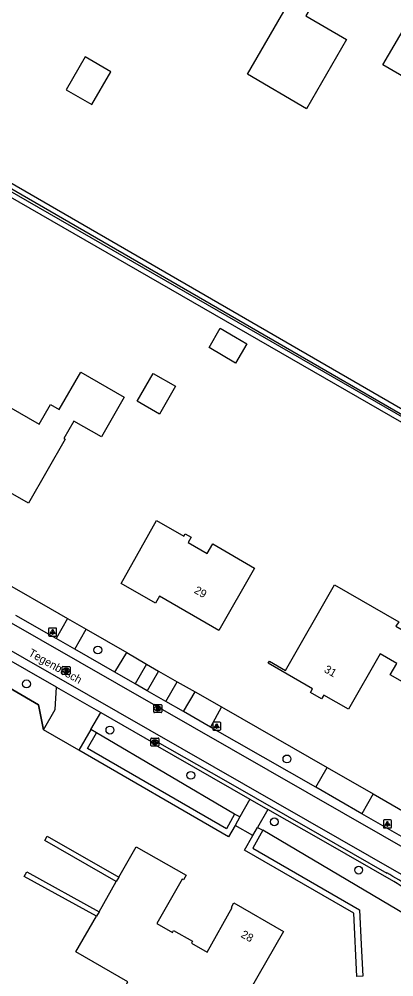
# Model space of a CAD drawing. Extents: x 156502 to 159074, y 384229 to 386094.
# Drawn here: x 157105.6 to 157152.4, y 385707.8 to 385827.5 of the extents above; entities that cross this region are included whole.
import ezdxf

# ---------------------------------------------------------------- set-up
doc = ezdxf.new("R2010")
doc.units = 0
for name, color, linetype in [('IMGEO_Berm_groen', 7, 'Continuous'), ('IMGEO_Berm_open', 7, 'Continuous'), ('IMGEO_Boom', 7, 'Continuous'), ('IMGEO_Brandkraan', 7, 'Continuous'), ('IMGEO_Erf', 7, 'Continuous'), ('IMGEO_Groenvoorziening', 7, 'Continuous'), ('IMGEO_Hek', 7, 'Continuous'), ('IMGEO_Kolk', 7, 'Continuous'), ('IMGEO_Lichtpunt', 7, 'Continuous'), ('IMGEO_Muur', 7, 'Continuous'), ('IMGEO_Openbare_ruimte_label', 7, 'Continuous'), ('IMGEO_Pand', 7, 'Continuous'), ('IMGEO_Pand_nummerreeks', 7, 'Continuous'), ('IMGEO_Rijbaan_lokaal_gesloten', 7, 'Continuous'), ('IMGEO_Rijbaan_lokaal_halfverhard', 7, 'Continuous'), ('IMGEO_Rijbaan_lokaal_open', 7, 'Continuous'), ('IMGEO_Rioolput', 7, 'Continuous'), ('IMGEO_Voetpad_open', 7, 'Continuous'), ('IMGEO_Waterloop', 7, 'Continuous')]:
    doc.layers.add(name, color=color, linetype=linetype)

msp = doc.modelspace()

# ---------------------------------------------------------------- linework, layer by layer
at = {"layer": 'IMGEO_Berm_groen'}
for points in [[(157149.86, 385730.69), (157157.49, 385726.3), (157201.73, 385802.69)], [(157104.7, 385756.59), (157109.52, 385753.85), (157111.68, 385752.61)], [(157114.02, 385751.26), (157119.09, 385748.36)], [(157121.52, 385746.89), (157123.02, 385746.04)], [(157125.38, 385744.7), (157127.6, 385743.44)], [(157130.92, 385741.58), (157131.2, 385741.42), (157144.11, 385733.99)], [(157132.53, 385728.17), (157115.29, 385738.33)]]:
    msp.add_lwpolyline(points, dxfattribs=at)
at = {"layer": 'IMGEO_Berm_open'}
for points in [[(157122.69, 385736.92), (157122.63, 385736.81), (157134.44, 385730.05)], [(157152.44, 385719.74), (157143.67, 385724.77), (157136.7, 385728.76)]]:
    msp.add_lwpolyline(points, dxfattribs=at)
msp.add_arc((157139.85, 385698.06), 25.07, 51.2051, 59.8606, dxfattribs=at)
at = {"layer": 'IMGEO_Boom'}
for centre in [(157115.46, 385748.66), (157106.55, 385744.43), (157116.97, 385738.66), (157139.08, 385735.06), (157127.07, 385733.01), (157137.51, 385727.2), (157148.05, 385721.17)]:
    msp.add_circle(centre, 0.489, dxfattribs=at)
at = {"layer": 'IMGEO_Brandkraan'}
for p, q in [((157111, 385745.67), (157111, 385746.53)), ((157111.07, 385746.6), (157111.92, 385746.6)), ((157111.49, 385746.38), (157111.51, 385746.38)), ((157112, 385746.53), (157112, 385745.67)), ((157111.92, 385745.6), (157111.07, 385745.6)), ((157111.51, 385745.82), (157111.48, 385745.82))]:
    msp.add_line(p, q, dxfattribs=at)
for points in [[(157111, 385745.67), (157111, 385746.53)], [(157111.07, 385746.6), (157111.92, 385746.6)], [(157111.34, 385746.3), (157111.34, 385745.9), (157111.56, 385745.9)], [(157111.58, 385746.3), (157111.34, 385746.3)], [(157112, 385746.53), (157112, 385745.67)], [(157111.92, 385745.6), (157111.07, 385745.6)], [(157111.52, 385746.22), (157111.47, 385746.22), (157111.47, 385746.14)], [(157111.47, 385746.14), (157111.52, 385746.14)], [(157111.53, 385746.07), (157111.47, 385746.07), (157111.47, 385745.99)], [(157111.47, 385745.99), (157111.53, 385745.99)]]:
    msp.add_lwpolyline(points, dxfattribs=at)
for centre, radius, start, end in [((157111.07, 385746.52), 0.0765, 91.552, 178.448), ((157111.07, 385746.52), 0.0765, 91.552, 178.448), ((157111.58, 385746.15), 0.145, 59.4692, 91.5367), ((157111.61, 385746.2), 0.0922, 285.5137, 58.1501), ((157111.92, 385746.52), 0.0765, 1.552, 88.448), ((157111.92, 385746.52), 0.0765, 1.552, 88.448), ((157111.07, 385745.68), 0.0765, 181.552, 268.448), ((157111.07, 385745.68), 0.0765, 181.552, 268.448), ((157111.52, 385746.18), 0.0379, 267.8285, 90.9355), ((157111.53, 385746.03), 0.0404, 269.8759, 90.5077), ((157111.56, 385746.15), 0.251, 268.6676, 293.5347), ((157111.61, 385746.01), 0.105, 301.3115, 78.989), ((157111.92, 385745.68), 0.0765, 271.552, 358.448), ((157111.92, 385745.68), 0.0765, 271.552, 358.448)]:
    msp.add_arc(centre, radius, start, end, dxfattribs=at)
for centre, major_axis, ratio, start_param, end_param in [((157111.48, 385746.1), (-0.387, 0.002), 0.722429, 4.712389, 7.853982), ((157111.51, 385746.1), (-0.39, 0.002), 0.717154, 1.570796, 4.712389)]:
    msp.add_ellipse(centre, major_axis=major_axis, ratio=ratio, start_param=start_param, end_param=end_param, dxfattribs=at)
at = {"layer": 'IMGEO_Erf'}
msp.add_lwpolyline([(157069.69, 385879.77), (157062.24, 385869.45), (157047.22, 385849.55), (157042.79, 385843.67), (157065.31, 385829.89), (157068.35, 385827.98), (157173.43, 385767.23), (157172.68, 385766.01), (157064.37, 385828.33), (157041.36, 385841.78), (157036.59, 385835.46)], dxfattribs=at)
at = {"layer": 'IMGEO_Groenvoorziening'}
for points in [[(157080.3, 385758.4), (157080.13, 385758.1), (157108.06, 385741.81), (157108.69, 385738.71)], [(157165.17, 385704.25), (157155.05, 385714.92), (157136.06, 385726.15)]]:
    msp.add_lwpolyline(points, dxfattribs=at)
at = {"layer": 'IMGEO_Hek'}
for points in [[(157149.86, 385730.69), (157157.49, 385726.3), (157201.73, 385802.69)], [(157108.69, 385738.71), (157108.06, 385741.81), (157080.13, 385758.1)], [(157104.7, 385756.59), (157109.52, 385753.85)], [(157131.2, 385741.42), (157144.11, 385733.99)], [(157144.11, 385733.99), (157149.86, 385730.69)]]:
    msp.add_lwpolyline(points, dxfattribs=at)
at = {"layer": 'IMGEO_Kolk'}
for p, q in [((157122.09, 385736.73), (157122.09, 385737.58)), ((157122.16, 385737.65), (157123.01, 385737.65)), ((157122.57, 385737.43), (157122.6, 385737.43)), ((157122.6, 385736.87), (157122.57, 385736.87)), ((157123.09, 385737.58), (157123.09, 385736.73)), ((157123.01, 385736.65), (157122.16, 385736.65))]:
    msp.add_line(p, q, dxfattribs=at)
for points in [[(157122.09, 385736.73), (157122.09, 385737.58)], [(157122.16, 385737.65), (157123.01, 385737.65)], [(157122.41, 385737.35), (157122.53, 385737.35), (157122.53, 385737.2), (157122.66, 385737.35), (157122.82, 385737.35), (157122.68, 385737.2), (157122.83, 385736.95), (157122.68, 385736.95), (157122.59, 385737.12), (157122.53, 385737.05), (157122.53, 385736.95), (157122.41, 385736.95), (157122.41, 385737.35)], [(157123.09, 385737.58), (157123.09, 385736.73)], [(157123.01, 385736.65), (157122.16, 385736.65)]]:
    msp.add_lwpolyline(points, dxfattribs=at)
for centre, start, end in [((157122.16, 385737.58), 91.552, 178.448), ((157122.16, 385737.58), 91.552, 178.448), ((157122.16, 385736.73), 181.552, 268.448), ((157122.16, 385736.73), 181.552, 268.448), ((157123.01, 385737.58), 1.552, 88.448), ((157123.01, 385737.58), 1.552, 88.448), ((157123.01, 385736.73), 271.552, 358.448), ((157123.01, 385736.73), 271.552, 358.448)]:
    msp.add_arc(centre, 0.0765, start, end, dxfattribs=at)
for centre, major_axis, ratio, start_param, end_param in [((157122.57, 385737.15), (-0.387, 0.002), 0.722429, 4.712389, 7.853982), ((157122.6, 385737.15), (-0.39, 0.002), 0.717154, 1.570796, 4.712389)]:
    msp.add_ellipse(centre, major_axis=major_axis, ratio=ratio, start_param=start_param, end_param=end_param, dxfattribs=at)
at = {"layer": 'IMGEO_Lichtpunt'}
for p, q in [((157109.31, 385751.31), (157109.31, 385750.5)), ((157109.31, 385751.31), (157109.31, 385750.5)), ((157110.21, 385751.4), (157109.41, 385751.4)), ((157110.21, 385751.4), (157109.41, 385751.4)), ((157110.31, 385750.5), (157110.31, 385751.31)), ((157110.31, 385750.5), (157110.31, 385751.31)), ((157109.41, 385750.41), (157110.21, 385750.41)), ((157109.41, 385750.41), (157110.21, 385750.41)), ((157129.81, 385739.56), (157129.81, 385738.75)), ((157129.81, 385739.56), (157129.81, 385738.75)), ((157130.71, 385739.65), (157129.91, 385739.65)), ((157130.71, 385739.65), (157129.91, 385739.65)), ((157130.81, 385738.75), (157130.81, 385739.56)), ((157130.81, 385738.75), (157130.81, 385739.56)), ((157129.91, 385738.65), (157130.71, 385738.65)), ((157129.91, 385738.65), (157130.71, 385738.65)), ((157151.13, 385727.34), (157151.13, 385726.54)), ((157151.13, 385727.34), (157151.13, 385726.54)), ((157152.03, 385727.44), (157151.23, 385727.44)), ((157152.03, 385727.44), (157151.23, 385727.44)), ((157152.13, 385726.54), (157152.13, 385727.34)), ((157152.13, 385726.54), (157152.13, 385727.34)), ((157151.23, 385726.44), (157152.03, 385726.44)), ((157151.23, 385726.44), (157152.03, 385726.44))]:
    msp.add_line(p, q, dxfattribs=at)
for points in [[(157109.69, 385750.97), (157109.72, 385750.95), (157109.54, 385750.68), (157109.5, 385750.71), (157109.69, 385750.97)], [(157109.79, 385750.93), (157109.84, 385750.93), (157109.84, 385750.6), (157109.79, 385750.6), (157109.79, 385750.93)], [(157109.9, 385750.95), (157109.94, 385750.97), (157110.12, 385750.71), (157110.08, 385750.68), (157109.9, 385750.95)], [(157130.19, 385739.22), (157130.22, 385739.19), (157130.04, 385738.93), (157130, 385738.96), (157130.19, 385739.22)], [(157130.29, 385739.17), (157130.33, 385739.17), (157130.33, 385738.85), (157130.29, 385738.85), (157130.29, 385739.17)], [(157130.4, 385739.19), (157130.44, 385739.22), (157130.62, 385738.96), (157130.58, 385738.93), (157130.4, 385739.19)], [(157151.51, 385727.01), (157151.54, 385726.98), (157151.36, 385726.72), (157151.32, 385726.74), (157151.51, 385727.01)], [(157151.61, 385726.96), (157151.65, 385726.96), (157151.65, 385726.64), (157151.61, 385726.64), (157151.61, 385726.96)], [(157151.72, 385726.98), (157151.76, 385727.01), (157151.94, 385726.74), (157151.9, 385726.72), (157151.72, 385726.98)]]:
    msp.add_lwpolyline(points, dxfattribs=at)
for centre in [(157109.81, 385751.11), (157130.31, 385739.35), (157151.63, 385727.14)]:
    msp.add_circle(centre, 0.0994, dxfattribs=at)
for centre, start, end in [((157109.41, 385751.31), 90, 180), ((157109.41, 385751.31), 90, 180), ((157110.21, 385751.31), 0, 90), ((157110.21, 385751.31), 0, 90), ((157109.41, 385750.5), 180, 270), ((157109.41, 385750.5), 180, 270), ((157110.21, 385750.5), 270, 0), ((157110.21, 385750.5), 270, 360), ((157129.91, 385739.56), 90, 180), ((157129.91, 385739.56), 90, 180), ((157130.71, 385739.56), 0, 90), ((157130.71, 385739.56), 0, 90), ((157129.91, 385738.75), 180, 270), ((157129.91, 385738.75), 180, 270), ((157130.71, 385738.75), 270, 0), ((157130.71, 385738.75), 270, 360), ((157151.23, 385727.34), 90, 180), ((157151.23, 385727.34), 90, 180), ((157152.03, 385727.34), 0, 90), ((157152.03, 385727.34), 0, 90), ((157151.23, 385726.54), 180, 270), ((157151.23, 385726.54), 180, 270), ((157152.03, 385726.54), 270, 0), ((157152.03, 385726.54), 270, 360)]:
    msp.add_arc(centre, 0.0946, start, end, dxfattribs=at)
at = {"layer": 'IMGEO_Muur'}
for points in [[(157114.59, 385738.74), (157113.08, 385736.14)], [(157132.53, 385728.17), (157131.53, 385726.33), (157114.18, 385736.38), (157115.29, 385738.33)], [(157115.29, 385738.33), (157114.59, 385738.74)], [(157132.6, 385726.76), (157131.79, 385725.32), (157113.08, 385736.14)], [(157133.19, 385727.82), (157132.53, 385728.17)], [(157133.19, 385727.82), (157132.6, 385726.76)], [(157136.06, 385726.15), (157134.82, 385723.92), (157148.15, 385716.22), (157148.36, 385711.9), (157148.56, 385707.92), (157147.81, 385707.89), (157147.43, 385715.81), (157133.77, 385723.65), (157134.82, 385725.48)], [(157134.82, 385725.48), (157135.42, 385726.51)], [(157135.42, 385726.51), (157136.06, 385726.15)], [(157117.76, 385719.73), (157108.82, 385724.86), (157109.14, 385725.43), (157118.08, 385720.3)], [(157115.28, 385715.42), (157106.27, 385720.37), (157106.58, 385720.95), (157115.61, 385715.98)]]:
    msp.add_lwpolyline(points, dxfattribs=at)
at = {"layer": 'IMGEO_Pand'}
for points in [[(157146.05, 385835.12), (157142.29, 385828.64), (157141.99, 385828.81), (157141.44, 385827.87), (157146.53, 385824.91), (157141.52, 385816.26), (157134.14, 385820.57), (157139.17, 385829.21), (157139.46, 385829.04), (157140, 385829.97), (157130.95, 385835.26), (157134.71, 385841.68)], [(157159.85, 385827.05), (157159.09, 385825.75), (157166.18, 385821.64), (157162.46, 385815.18), (157162.23, 385815.32), (157161.73, 385814.45), (157166.7, 385811.49), (157163.33, 385805.74), (157155.96, 385810.06), (157159.32, 385815.82), (157159.7, 385815.6), (157160.2, 385816.47), (157151.08, 385821.77), (157155.6, 385829.52)], [(157111.49, 385818.64), (157114.69, 385816.79), (157117.07, 385820.9), (157113.86, 385822.75), (157111.49, 385818.64)], [(157132.67, 385787.73), (157134.07, 385786.91), (157132.67, 385784.51), (157129.35, 385786.45), (157130.74, 385788.85), (157132.67, 385787.73)], [(157113.32, 385783.38), (157118.76, 385780.24), (157115.91, 385775.3), (157112.47, 385777.26), (157111.23, 385775.08), (157111.36, 385775), (157106.78, 385767.01), (157095.84, 385773.27), (157097.37, 385775.94), (157097.01, 385776.17), (157098.05, 385777.99), (157098.42, 385777.78), (157100.43, 385781.28), (157108.12, 385776.86), (157109.54, 385779.34), (157110.64, 385778.71), (157113.32, 385783.38)], [(157122.39, 385783.21), (157125.16, 385781.61), (157123.15, 385778.13), (157120.38, 385779.73), (157122.39, 385783.21)], [(157135.02, 385758.88), (157130.57, 385751.11), (157123.15, 385755.39), (157122.66, 385754.53), (157118.38, 385756.99), (157122.78, 385764.83), (157126.21, 385762.9), (157126.36, 385763.17), (157127.1, 385762.74), (157126.73, 385762.11), (157129.13, 385760.73), (157129.83, 385761.93), (157135.02, 385758.88)], [(157145.01, 385756.81), (157153.04, 385752.2), (157152.68, 385751.64), (157154.77, 385750.43), (157156.17, 385752.87), (157159.74, 385750.83), (157155.57, 385743.53), (157151.99, 385745.57), (157152.8, 385746.98), (157150.71, 385748.19), (157146.76, 385741.27), (157143.69, 385743.03), (157143.42, 385742.57), (157142.02, 385743.36), (157142.29, 385743.83), (157136.74, 385747), (157136.9, 385747.28), (157138.9, 385746.11), (157145.01, 385756.81)], [(157118.08, 385720.3), (157120.26, 385724.08), (157126.49, 385720.54), (157126.14, 385719.95), (157125.99, 385720.04), (157122.81, 385714.52), (157124.77, 385713.36), (157124.93, 385713.64), (157127.28, 385712.29), (157127.14, 385712.03), (157129.12, 385710.91), (157132.23, 385716.49), (157132.14, 385716.54), (157132.45, 385717.08), (157138.64, 385713.52), (157131.1, 385700.4), (157124.6, 385704.14), (157122.17, 385699.91), (157116.79, 385703), (157119.22, 385707.23), (157112.72, 385710.97), (157115.28, 385715.42)], [(157118.08, 385720.3), (157117.76, 385719.73)], [(157115.61, 385715.98), (157117.76, 385719.73)], [(157115.61, 385715.98), (157115.28, 385715.42)]]:
    msp.add_lwpolyline(points, dxfattribs=at)
at = {"layer": 'IMGEO_Rijbaan_lokaal_gesloten'}
for points in [[(157042.42, 385787.66), (157155.6, 385722.87)], [(157153.39, 385720.62), (157047.47, 385781.29)]]:
    msp.add_lwpolyline(points, dxfattribs=at)
at = {"layer": 'IMGEO_Rijbaan_lokaal_halfverhard'}
for points in [[(157110.28, 385744.04), (157081.5, 385760.5)], [(157110.24, 385750.1), (157105.2, 385752.99)], [(157117.59, 385745.88), (157112.58, 385748.76)], [(157121.61, 385743.58), (157120.12, 385744.43)], [(157126.18, 385740.97), (157123.97, 385742.23)], [(157115.82, 385740.86), (157122.69, 385736.92)], [(157142.68, 385731.52), (157129.53, 385739.04)], [(157122.69, 385736.92), (157122.86, 385737.21), (157131.14, 385732.5), (157143.14, 385725.64), (157151.56, 385720.81)], [(157156.01, 385723.89), (157148.43, 385728.2)]]:
    msp.add_lwpolyline(points, dxfattribs=at)
msp.add_arc((157132.49, 385686.22), 39.5, 51.0824, 61.1429, dxfattribs=at)
at = {"layer": 'IMGEO_Rijbaan_lokaal_open'}
for points in [[(157111.68, 385752.61), (157110.24, 385750.1)], [(157111.68, 385752.61), (157114.02, 385751.26)], [(157112.58, 385748.76), (157114.02, 385751.26)], [(157112.58, 385748.76), (157110.24, 385750.1)], [(157117.59, 385745.88), (157119.09, 385748.36)], [(157119.09, 385748.36), (157121.52, 385746.89)], [(157121.52, 385746.89), (157120.12, 385744.43)], [(157120.12, 385744.43), (157117.59, 385745.88)], [(157123.02, 385746.04), (157121.61, 385743.58)], [(157123.02, 385746.04), (157125.38, 385744.7)], [(157108.69, 385738.71), (157110.12, 385741.22), (157110.28, 385744.04)], [(157110.28, 385744.04), (157115.82, 385740.86)], [(157123.97, 385742.23), (157125.38, 385744.7)], [(157123.97, 385742.23), (157121.61, 385743.58)], [(157126.18, 385740.97), (157127.6, 385743.44)], [(157127.6, 385743.44), (157130.92, 385741.58)], [(157130.92, 385741.58), (157129.53, 385739.04)], [(157114.59, 385738.74), (157115.82, 385740.86)], [(157129.53, 385739.04), (157126.18, 385740.97)], [(157113.08, 385736.14), (157108.69, 385738.71)], [(157142.68, 385731.52), (157144.11, 385733.99)], [(157144.11, 385733.99), (157149.86, 385730.69)], [(157148.43, 385728.2), (157142.68, 385731.52)], [(157149.86, 385730.69), (157148.43, 385728.2)]]:
    msp.add_lwpolyline(points, dxfattribs=at)
at = {"layer": 'IMGEO_Rioolput'}
for p, q in [((157122.44, 385740.93), (157122.44, 385741.79)), ((157122.52, 385741.86), (157123.37, 385741.86)), ((157122.93, 385741.64), (157122.96, 385741.64)), ((157123.45, 385741.79), (157123.45, 385740.93)), ((157123.37, 385740.86), (157122.52, 385740.86)), ((157122.95, 385741.08), (157122.93, 385741.08))]:
    msp.add_line(p, q, dxfattribs=at)
for points in [[(157122.44, 385740.93), (157122.44, 385741.79)], [(157122.52, 385741.86), (157123.37, 385741.86)], [(157123.03, 385741.56), (157122.78, 385741.56), (157122.78, 385741.16)], [(157122.96, 385741.48), (157122.91, 385741.48), (157122.91, 385741.4)], [(157123.45, 385741.79), (157123.45, 385740.93)], [(157123.37, 385740.86), (157122.52, 385740.86)], [(157122.78, 385741.16), (157122.91, 385741.16), (157122.91, 385741.32), (157122.92, 385741.32)], [(157122.91, 385741.4), (157122.96, 385741.4)], [(157122.96, 385741.29), (157123.03, 385741.16), (157123.17, 385741.16), (157123.11, 385741.29)]]:
    msp.add_lwpolyline(points, dxfattribs=at)
for centre, radius, start, end in [((157122.52, 385741.78), 0.0765, 91.552, 178.448), ((157122.52, 385741.78), 0.0765, 91.552, 178.448), ((157122.96, 385741.38), 0.0964, 77.0061, 93.1865), ((157122.98, 385741.44), 0.0378, 276.6634, 79.6772), ((157123.03, 385741.45), 0.109, 350.3612, 89.416), ((157123.37, 385741.78), 0.0765, 1.552, 88.448), ((157123.37, 385741.78), 0.0765, 1.552, 88.448), ((157122.52, 385740.93), 0.0765, 181.552, 268.448), ((157122.52, 385740.93), 0.0765, 181.552, 268.448), ((157122.91, 385741.27), 0.0533, 26.0293, 88.6989), ((157122.94, 385741.59), 0.19, 274.7715, 282.9687), ((157123.03, 385741.45), 0.112, 277.5842, 350.9817), ((157123.01, 385741.23), 0.108, 29.5134, 73.7905), ((157123.37, 385740.93), 0.0765, 271.552, 358.448), ((157123.37, 385740.93), 0.0765, 271.552, 358.448)]:
    msp.add_arc(centre, radius, start, end, dxfattribs=at)
for centre, major_axis, ratio, start_param, end_param in [((157122.93, 385741.36), (-0.387, 0.002), 0.722429, 4.712389, 7.853982), ((157122.96, 385741.36), (-0.39, 0.002), 0.717154, 1.570796, 4.712389)]:
    msp.add_ellipse(centre, major_axis=major_axis, ratio=ratio, start_param=start_param, end_param=end_param, dxfattribs=at)
at = {"layer": 'IMGEO_Voetpad_open'}
for points in [[(157134.44, 385730.05), (157133.19, 385727.82)], [(157134.44, 385730.05), (157136.7, 385728.76)], [(157136.7, 385728.76), (157135.42, 385726.51)], [(157134.82, 385725.48), (157132.6, 385726.76)]]:
    msp.add_lwpolyline(points, dxfattribs=at)
at = {"layer": 'IMGEO_Waterloop'}
msp.add_lwpolyline([(157064.99, 385829.36), (157068.02, 385827.45), (157172.57, 385767.01), (157172.47, 385766.85), (157064.68, 385828.86)], dxfattribs=at)

# ---------------------------------------------------------------- texts
at = {"layer": 'IMGEO_Openbare_ruimte_label'}
msp.add_text('Tegenbosch', height=1, rotation=330.5892, dxfattribs=at).set_placement((157106.7, 385748.02))
at = {"layer": 'IMGEO_Pand_nummerreeks'}
for s, rotation, p in [('29', 330.0342, (157127.4, 385755.85)), ('31', 330.1526, (157143.63, 385745.97)), ('28', 331.0736, (157133.24, 385712.85))]:
    msp.add_text(s, height=1, rotation=rotation, dxfattribs=at).set_placement(p)

doc.saveas('drawing.dxf')
